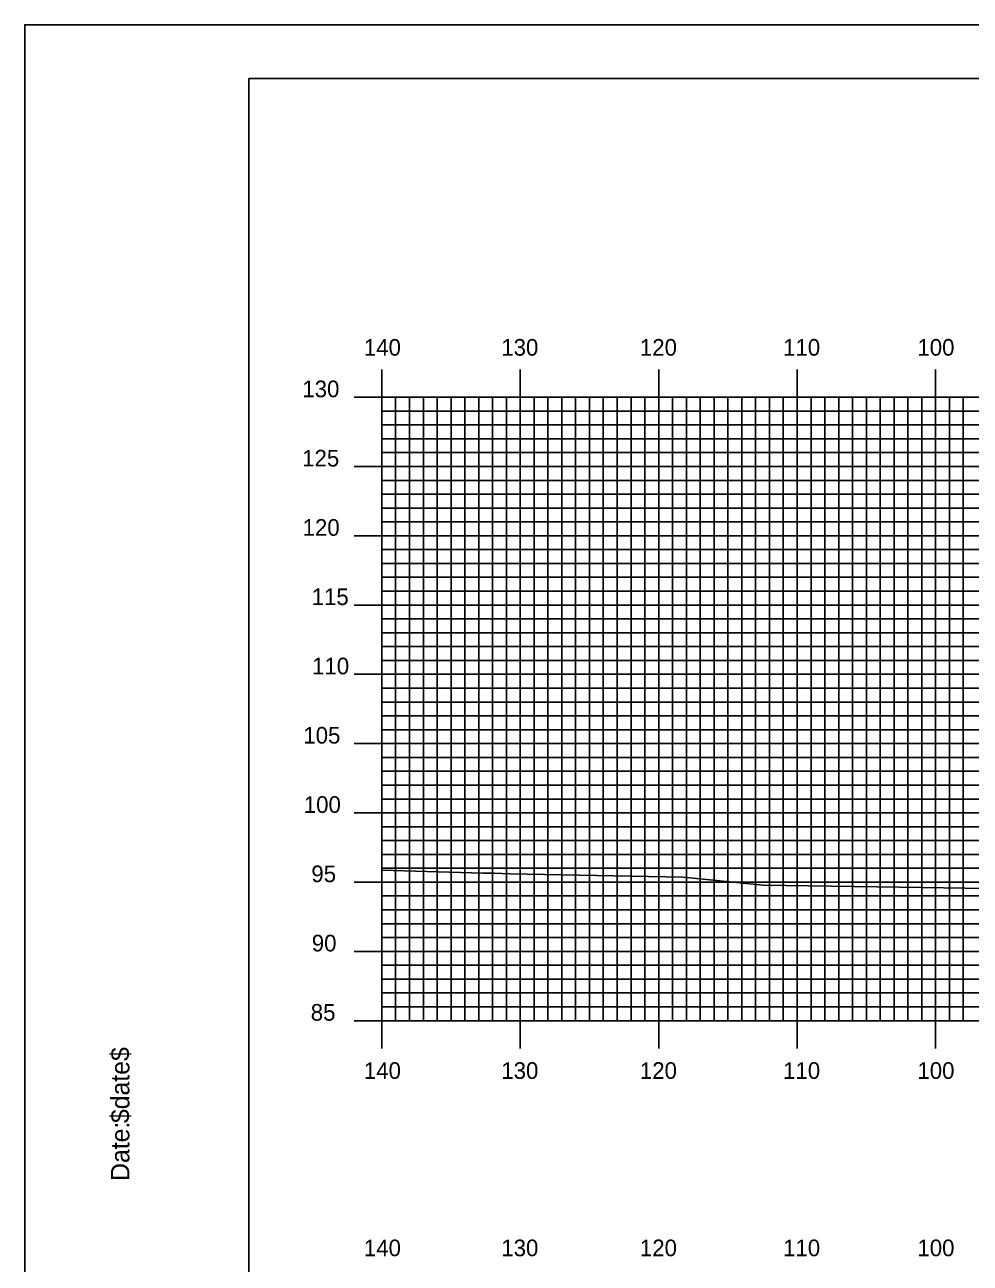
# Model space of a CAD drawing. Extents: x 1785795 to 1786139, y 442591 to 442811.
# Drawn here: x 1785795.3 to 1785863.6, y 442721.2 to 442810.5 of the extents above; entities that cross this region are included whole.
import ezdxf

# ---------------------------------------------------------------- set-up
doc = ezdxf.new("R2010")
doc.units = 0
for name, color, linetype in [('BORDER', 7, 'Continuous'), ('H_V ANNOTATION', 7, 'Continuous'), ('MAJOR', 7, 'Continuous'), ('MINOR', 7, 'Continuous'), ('PLOT BOUNDARY', 7, 'Continuous'), ('S_Roadway_Centerline', 7, 'Continuous')]:
    doc.layers.add(name, color=color, linetype=linetype)

msp = doc.modelspace()

# ---------------------------------------------------------------- linework, layer by layer
at = {"layer": 'BORDER'}
msp.add_lwpolyline([(1785811.452, 442596.665), (1786131.452, 442596.665), (1786131.452, 442806.665), (1785811.452, 442806.665)], close=True, dxfattribs=at)
at = {"layer": 'MAJOR'}
for p, q in [((1785821.052, 442785.669), (1785821.052, 442783.665)), ((1785831.052, 442785.669), (1785831.052, 442783.665)), ((1785841.052, 442785.669), (1785841.052, 442783.665)), ((1785851.052, 442785.669), (1785851.052, 442783.665)), ((1785861.052, 442785.669), (1785861.052, 442783.665)), ((1785819.048, 442783.665), (1785821.052, 442783.665)), ((1785821.052, 442783.665), (1786101.052, 442783.665)), ((1785821.052, 442738.665), (1785821.052, 442783.665)), ((1785821.052, 442738.665), (1785821.052, 442783.665)), ((1785821.052, 442783.665), (1786101.052, 442783.665)), ((1785831.052, 442738.665), (1785831.052, 442783.665)), ((1785841.052, 442738.665), (1785841.052, 442783.665)), ((1785851.052, 442738.665), (1785851.052, 442783.665)), ((1785861.052, 442738.665), (1785861.052, 442783.665)), ((1785819.048, 442778.665), (1785821.052, 442778.665)), ((1785821.052, 442778.665), (1786101.052, 442778.665)), ((1785819.048, 442773.665), (1785821.052, 442773.665)), ((1785821.052, 442773.665), (1786101.052, 442773.665)), ((1785819.048, 442768.665), (1785821.052, 442768.665)), ((1785821.052, 442768.665), (1786101.052, 442768.665)), ((1785819.048, 442763.665), (1785821.052, 442763.665)), ((1785821.052, 442763.665), (1786101.052, 442763.665)), ((1785819.048, 442758.665), (1785821.052, 442758.665)), ((1785821.052, 442758.665), (1786101.052, 442758.665)), ((1785819.048, 442753.665), (1785821.052, 442753.665)), ((1785821.052, 442753.665), (1786101.052, 442753.665)), ((1785819.048, 442748.665), (1785821.052, 442748.665)), ((1785821.052, 442748.665), (1786101.052, 442748.665)), ((1785819.048, 442743.665), (1785821.052, 442743.665)), ((1785821.052, 442743.665), (1786101.052, 442743.665)), ((1785819.048, 442738.665), (1785821.052, 442738.665)), ((1785821.052, 442738.665), (1786101.052, 442738.665)), ((1785821.052, 442738.665), (1786101.052, 442738.665)), ((1785821.052, 442736.661), (1785821.052, 442738.665)), ((1785831.052, 442736.661), (1785831.052, 442738.665)), ((1785841.052, 442736.661), (1785841.052, 442738.665)), ((1785851.052, 442736.661), (1785851.052, 442738.665)), ((1785861.052, 442736.661), (1785861.052, 442738.665))]:
    msp.add_line(p, q, dxfattribs=at)
at = {"layer": 'MINOR'}
for p, q in [((1785822.052, 442738.665), (1785822.052, 442783.665)), ((1785823.052, 442738.665), (1785823.052, 442783.665)), ((1785824.052, 442738.665), (1785824.052, 442783.665)), ((1785825.052, 442738.665), (1785825.052, 442783.665)), ((1785826.052, 442738.665), (1785826.052, 442783.665)), ((1785827.052, 442738.665), (1785827.052, 442783.665)), ((1785828.052, 442738.665), (1785828.052, 442783.665)), ((1785829.052, 442738.665), (1785829.052, 442783.665)), ((1785830.052, 442738.665), (1785830.052, 442783.665)), ((1785832.052, 442738.665), (1785832.052, 442783.665)), ((1785833.052, 442738.665), (1785833.052, 442783.665)), ((1785834.052, 442738.665), (1785834.052, 442783.665)), ((1785835.052, 442738.665), (1785835.052, 442783.665)), ((1785836.052, 442738.665), (1785836.052, 442783.665)), ((1785837.052, 442738.665), (1785837.052, 442783.665)), ((1785838.052, 442738.665), (1785838.052, 442783.665)), ((1785839.052, 442738.665), (1785839.052, 442783.665)), ((1785840.052, 442738.665), (1785840.052, 442783.665)), ((1785842.052, 442738.665), (1785842.052, 442783.665)), ((1785843.052, 442738.665), (1785843.052, 442783.665)), ((1785844.052, 442738.665), (1785844.052, 442783.665)), ((1785845.052, 442738.665), (1785845.052, 442783.665)), ((1785846.052, 442738.665), (1785846.052, 442783.665)), ((1785847.052, 442738.665), (1785847.052, 442783.665)), ((1785848.052, 442738.665), (1785848.052, 442783.665)), ((1785849.052, 442738.665), (1785849.052, 442783.665)), ((1785850.052, 442738.665), (1785850.052, 442783.665)), ((1785852.052, 442738.665), (1785852.052, 442783.665)), ((1785853.052, 442738.665), (1785853.052, 442783.665)), ((1785854.052, 442738.665), (1785854.052, 442783.665)), ((1785855.052, 442738.665), (1785855.052, 442783.665)), ((1785856.052, 442738.665), (1785856.052, 442783.665)), ((1785857.052, 442738.665), (1785857.052, 442783.665)), ((1785858.052, 442738.665), (1785858.052, 442783.665)), ((1785859.052, 442738.665), (1785859.052, 442783.665)), ((1785860.052, 442738.665), (1785860.052, 442783.665)), ((1785862.052, 442738.665), (1785862.052, 442783.665)), ((1785863.052, 442738.665), (1785863.052, 442783.665)), ((1785821.052, 442782.665), (1786101.052, 442782.665)), ((1785821.052, 442782.665), (1785823.056, 442782.665)), ((1785821.052, 442781.665), (1786101.052, 442781.665)), ((1785821.052, 442781.665), (1785823.056, 442781.665)), ((1785821.052, 442780.665), (1786101.052, 442780.665)), ((1785821.052, 442780.665), (1785823.056, 442780.665)), ((1785821.052, 442779.665), (1786101.052, 442779.665)), ((1785821.052, 442779.665), (1785823.056, 442779.665)), ((1785821.052, 442777.665), (1786101.052, 442777.665)), ((1785821.052, 442777.665), (1785823.056, 442777.665)), ((1785821.052, 442776.665), (1786101.052, 442776.665)), ((1785821.052, 442776.665), (1785823.056, 442776.665)), ((1785821.052, 442775.665), (1786101.052, 442775.665)), ((1785821.052, 442775.665), (1785823.056, 442775.665)), ((1785821.052, 442774.665), (1786101.052, 442774.665)), ((1785821.052, 442774.665), (1785823.056, 442774.665)), ((1785821.052, 442772.665), (1786101.052, 442772.665)), ((1785821.052, 442772.665), (1785823.056, 442772.665)), ((1785821.052, 442771.665), (1786101.052, 442771.665)), ((1785821.052, 442771.665), (1785823.056, 442771.665)), ((1785821.052, 442770.665), (1786101.052, 442770.665)), ((1785821.052, 442770.665), (1785823.056, 442770.665)), ((1785821.052, 442769.665), (1786101.052, 442769.665)), ((1785821.052, 442769.665), (1785823.056, 442769.665)), ((1785821.052, 442767.665), (1786101.052, 442767.665)), ((1785821.052, 442767.665), (1785823.056, 442767.665)), ((1785821.052, 442766.665), (1786101.052, 442766.665)), ((1785821.052, 442766.665), (1785823.056, 442766.665)), ((1785821.052, 442765.665), (1786101.052, 442765.665)), ((1785821.052, 442765.665), (1785823.056, 442765.665)), ((1785821.052, 442764.665), (1786101.052, 442764.665)), ((1785821.052, 442764.665), (1785823.056, 442764.665)), ((1785821.052, 442762.665), (1786101.052, 442762.665)), ((1785821.052, 442762.665), (1785823.056, 442762.665)), ((1785821.052, 442761.665), (1786101.052, 442761.665)), ((1785821.052, 442761.665), (1785823.056, 442761.665)), ((1785821.052, 442760.665), (1786101.052, 442760.665)), ((1785821.052, 442760.665), (1785823.056, 442760.665)), ((1785821.052, 442759.665), (1786101.052, 442759.665)), ((1785821.052, 442759.665), (1785823.056, 442759.665)), ((1785821.052, 442757.665), (1786101.052, 442757.665)), ((1785821.052, 442757.665), (1785823.056, 442757.665)), ((1785821.052, 442756.665), (1786101.052, 442756.665)), ((1785821.052, 442756.665), (1785823.056, 442756.665)), ((1785821.052, 442755.665), (1786101.052, 442755.665)), ((1785821.052, 442755.665), (1785823.056, 442755.665)), ((1785821.052, 442754.665), (1786101.052, 442754.665)), ((1785821.052, 442754.665), (1785823.056, 442754.665)), ((1785821.052, 442752.665), (1786101.052, 442752.665)), ((1785821.052, 442752.665), (1785823.056, 442752.665)), ((1785821.052, 442751.665), (1786101.052, 442751.665)), ((1785821.052, 442751.665), (1785823.056, 442751.665)), ((1785821.052, 442750.665), (1786101.052, 442750.665)), ((1785821.052, 442750.665), (1785823.056, 442750.665)), ((1785821.052, 442749.665), (1786101.052, 442749.665)), ((1785821.052, 442749.665), (1785823.056, 442749.665)), ((1785821.052, 442747.665), (1786101.052, 442747.665)), ((1785821.052, 442747.665), (1785823.056, 442747.665)), ((1785821.052, 442746.665), (1786101.052, 442746.665)), ((1785821.052, 442746.665), (1785823.056, 442746.665)), ((1785821.052, 442745.665), (1786101.052, 442745.665)), ((1785821.052, 442745.665), (1785823.056, 442745.665)), ((1785821.052, 442744.665), (1786101.052, 442744.665)), ((1785821.052, 442744.665), (1785823.056, 442744.665)), ((1785821.052, 442742.665), (1786101.052, 442742.665)), ((1785821.052, 442742.665), (1785823.056, 442742.665)), ((1785821.052, 442741.665), (1786101.052, 442741.665)), ((1785821.052, 442741.665), (1785823.056, 442741.665)), ((1785821.052, 442740.665), (1786101.052, 442740.665)), ((1785821.052, 442740.665), (1785823.056, 442740.665)), ((1785821.052, 442739.665), (1786101.052, 442739.665)), ((1785821.052, 442739.665), (1785823.056, 442739.665))]:
    msp.add_line(p, q, dxfattribs=at)
at = {"layer": 'PLOT BOUNDARY'}
msp.add_lwpolyline([(1785795.265, 442590.547), (1786135.265, 442590.547), (1786135.265, 442810.547), (1785795.265, 442810.547)], close=True, dxfattribs=at)
at = {"layer": 'S_Roadway_Centerline'}
msp.add_lwpolyline([(1785821.052, 442749.519), (1785828.346, 442749.303), (1785829.166, 442749.301), (1785830.294, 442749.26), (1785842.808, 442749.026), (1785848.604, 442748.444), (1785860.082, 442748.287), (1785866.297, 442748.179)], dxfattribs=at)

# ---------------------------------------------------------------- texts
at = {"layer": 'BORDER'}
for s, p in [('$date$', (1785802.822, 442731.275)), ('Date:', (1785802.822, 442727.099))]:
    msp.add_text(s, height=1.3392, rotation=90, dxfattribs=at).set_placement(p)
at = {"layer": 'H_V ANNOTATION'}
for s, p in [('140', (1785819.757, 442786.665)), ('130', (1785829.682, 442786.665)), ('120', (1785839.692, 442786.665)), ('110', (1785850.035, 442786.665)), ('100', (1785859.735, 442786.665)), ('130', (1785815.312, 442783.665)), ('125', (1785815.301, 442778.665)), ('120', (1785815.333, 442773.665)), ('115', (1785815.986, 442768.665)), ('110', (1785816.018, 442763.665)), ('105', (1785815.386, 442758.665)), ('100', (1785815.418, 442753.665)), ('95', (1785815.964, 442748.665)), ('90', (1785815.996, 442743.665)), ('85', (1785815.921, 442738.665)), ('140', (1785819.757, 442734.465)), ('130', (1785829.682, 442734.465)), ('120', (1785839.692, 442734.465)), ('110', (1785850.035, 442734.465)), ('100', (1785859.735, 442734.465)), ('140', (1785819.757, 442721.665)), ('130', (1785829.682, 442721.665)), ('120', (1785839.692, 442721.665)), ('110', (1785850.035, 442721.665)), ('100', (1785859.735, 442721.665))]:
    msp.add_text(s, height=1.2, dxfattribs=at).set_placement(p)
at = {"layer": 'MAJOR'}
msp.add_text('-', height=0.012, dxfattribs=at).set_placement((1785821.043, 442738.665))

doc.saveas('drawing.dxf')
